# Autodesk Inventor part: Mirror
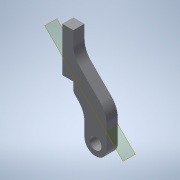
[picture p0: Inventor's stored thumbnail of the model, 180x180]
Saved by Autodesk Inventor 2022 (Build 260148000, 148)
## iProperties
Created: 2013-12
Part Number: Mirror
Material: Generic
Document SubType Name: Modeling
Designer: John
Density: 1 g/cm^3
Appearance: Default
Author: John
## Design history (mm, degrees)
sketch "Sketch1"
  geometry: L1 (0, 0)-(6.35, 0); L2 (6.35, 0)-(6.35, 25.4); L3 (6.35, 25.4)-(0, 25.4); L4 (0, 25.4)-(0, 0); L5 (6.35, 0)-(6.35, -5.261); L6 (6.35, -5.261)-(12.7, -11.611); L7 (12.7, -11.611)-(12.7, -24.311); L8 (25.4, -24.311)-(25.4, -6.35); L9 (25.4, -6.35)-(6.35, 12.7); A1 r 6.35 centre (19.05, -24.311) between (12.7, -24.311) and (25.4, -24.311)
  constraints: 18 end point, 6 parallel, 2 midpoint, 2 point on circle, 2 tangent, 1 centre point, 1 horizontal, 1 perpendicular, 1 point on line
  dimensions: "d0" = 6.35 distance of L3.end L2.end; "d1" = 25.4 distance of L2.end L1.end; "d2" = 6.35 radius of A1; "d3" = 12.7 distance between parallel lines of L9 L6; "d4" = 12.7 distance from line of A1.centre L2; "d5" = 45 deg angle of L9 L2
extrude "Extrusion1" new body sketch "Sketch1" distance "d6" = 6.35; taper "d7" = 0 deg
fillet "Fillet1" dims "d8" = 3.175
fillet "Fillet2" dims "d9" = 12.7
sketch "Sketch2"
  geometry: A1 r 6.35 centre (19.05, -24.311) between (12.7, -24.311) and (25.4, -24.311) reference
hole "Hole1" sketch "Sketch2" at (19.05, -24.311) diameter "d10" = 6.7564; stored, may be unused: countersink angle "d14" = 82 deg, drill point angle "d16" = 118 deg; dims "d11" = 19.05, "d12" = 11.1252, "d13" = 6.35, "d15" = 25.4
workplane "Work Plane1"
body "Solid1"
